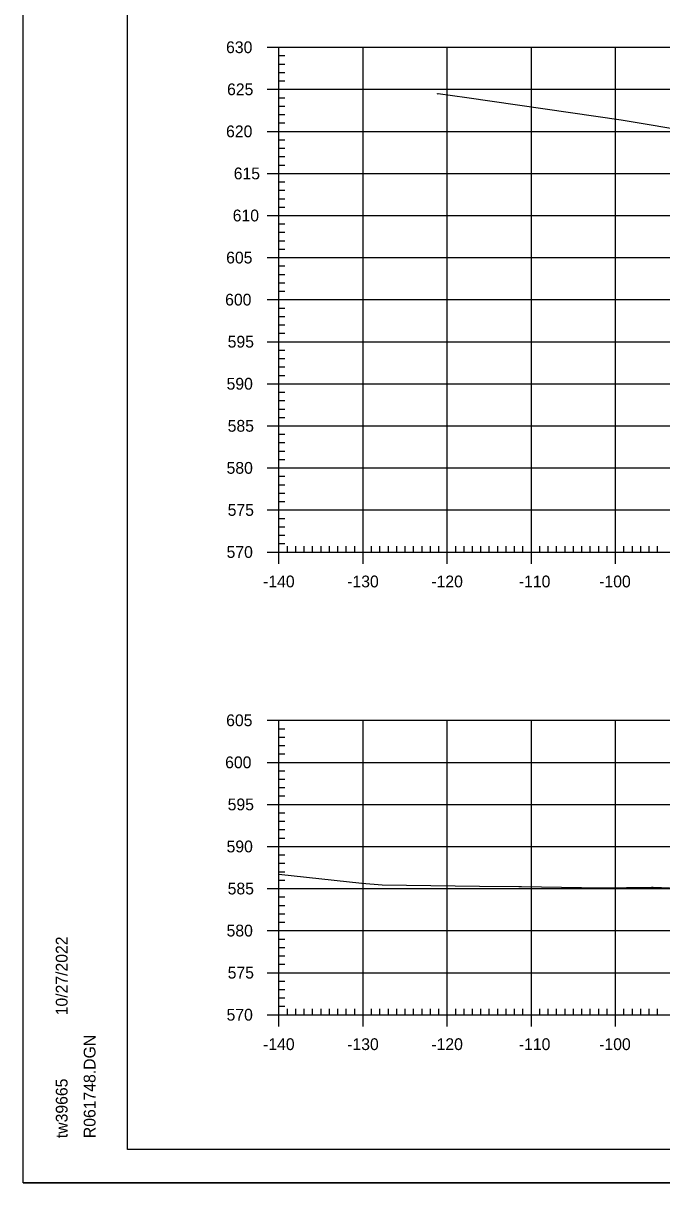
# Model space of a CAD drawing. Extents: x 961436 to 1372525, y 380079 to 2027791.
# Drawn here: x 1370463.4 to 1370539.3, y 380535.8 to 380673.6 of the extents above; entities that cross this region are included whole.
import ezdxf

# ---------------------------------------------------------------- set-up
doc = ezdxf.new("R2010")
doc.units = 0
for name, color, linetype in [('R_Axis', 7, 'Continuous'), ('R_Axis Annot', 7, 'Continuous'), ('R_Exist Surface', 7, 'Continuous'), ('R_Grid', 7, 'Continuous'), ('R_No Plot', 7, 'Continuous')]:
    doc.layers.add(name, color=color, linetype=linetype)

msp = doc.modelspace()

# ---------------------------------------------------------------- linework, layer by layer
at = {"layer": 'R_Axis'}
for p, q in [((1370492.41, 380670.73), (1370495.21, 380670.73)), ((1370493.81, 380610.73), (1370493.81, 380670.73)), ((1370493.81, 380669.73), (1370494.51, 380669.73)), ((1370493.81, 380668.73), (1370494.51, 380668.73)), ((1370493.81, 380667.73), (1370494.51, 380667.73)), ((1370493.81, 380666.73), (1370494.51, 380666.73)), ((1370492.41, 380665.73), (1370495.21, 380665.73)), ((1370493.81, 380664.73), (1370494.51, 380664.73)), ((1370493.81, 380663.73), (1370494.51, 380663.73)), ((1370493.81, 380662.73), (1370494.51, 380662.73)), ((1370493.81, 380661.73), (1370494.51, 380661.73)), ((1370492.41, 380660.73), (1370495.21, 380660.73)), ((1370493.81, 380659.73), (1370494.51, 380659.73)), ((1370493.81, 380658.73), (1370494.51, 380658.73)), ((1370493.81, 380657.73), (1370494.51, 380657.73)), ((1370493.81, 380656.73), (1370494.51, 380656.73)), ((1370492.41, 380655.73), (1370495.21, 380655.73)), ((1370493.81, 380654.73), (1370494.51, 380654.73)), ((1370493.81, 380653.73), (1370494.51, 380653.73)), ((1370493.81, 380652.73), (1370494.51, 380652.73)), ((1370493.81, 380651.73), (1370494.51, 380651.73)), ((1370492.41, 380650.73), (1370495.21, 380650.73)), ((1370493.81, 380649.73), (1370494.51, 380649.73)), ((1370493.81, 380648.73), (1370494.51, 380648.73)), ((1370493.81, 380647.73), (1370494.51, 380647.73)), ((1370492.41, 380645.73), (1370495.21, 380645.73)), ((1370493.81, 380646.73), (1370494.51, 380646.73)), ((1370493.81, 380644.73), (1370494.51, 380644.73)), ((1370493.81, 380643.73), (1370494.51, 380643.73)), ((1370493.81, 380642.73), (1370494.51, 380642.73)), ((1370493.81, 380641.73), (1370494.51, 380641.73)), ((1370492.41, 380640.73), (1370495.21, 380640.73)), ((1370493.81, 380639.73), (1370494.51, 380639.73)), ((1370493.81, 380638.73), (1370494.51, 380638.73)), ((1370493.81, 380637.73), (1370494.51, 380637.73)), ((1370493.81, 380636.73), (1370494.51, 380636.73)), ((1370492.41, 380635.73), (1370495.21, 380635.73)), ((1370493.81, 380634.73), (1370494.51, 380634.73)), ((1370493.81, 380633.73), (1370494.51, 380633.73)), ((1370493.81, 380632.73), (1370494.51, 380632.73)), ((1370492.41, 380630.73), (1370495.21, 380630.73)), ((1370493.81, 380631.73), (1370494.51, 380631.73)), ((1370493.81, 380629.73), (1370494.51, 380629.73)), ((1370493.81, 380628.73), (1370494.51, 380628.73)), ((1370493.81, 380627.73), (1370494.51, 380627.73)), ((1370493.81, 380626.73), (1370494.51, 380626.73)), ((1370492.41, 380625.73), (1370495.21, 380625.73)), ((1370493.81, 380624.73), (1370494.51, 380624.73)), ((1370493.81, 380623.73), (1370494.51, 380623.73)), ((1370493.81, 380622.73), (1370494.51, 380622.73)), ((1370493.81, 380621.73), (1370494.51, 380621.73)), ((1370492.41, 380620.73), (1370495.21, 380620.73)), ((1370493.81, 380619.73), (1370494.51, 380619.73)), ((1370493.81, 380618.73), (1370494.51, 380618.73)), ((1370493.81, 380617.73), (1370494.51, 380617.73)), ((1370493.81, 380616.73), (1370494.51, 380616.73)), ((1370492.41, 380615.73), (1370495.21, 380615.73)), ((1370493.81, 380614.73), (1370494.51, 380614.73)), ((1370493.81, 380613.73), (1370494.51, 380613.73)), ((1370493.81, 380612.73), (1370494.51, 380612.73)), ((1370493.81, 380609.33), (1370493.81, 380612.13)), ((1370493.81, 380611.73), (1370494.51, 380611.73)), ((1370494.81, 380610.73), (1370494.81, 380611.43)), ((1370495.81, 380610.73), (1370495.81, 380611.43)), ((1370496.81, 380610.73), (1370496.81, 380611.43)), ((1370497.81, 380610.73), (1370497.81, 380611.43)), ((1370498.81, 380610.73), (1370498.81, 380611.43)), ((1370499.81, 380610.73), (1370499.81, 380611.43)), ((1370500.81, 380610.73), (1370500.81, 380611.43)), ((1370501.81, 380610.73), (1370501.81, 380611.43)), ((1370502.81, 380610.73), (1370502.81, 380611.43)), ((1370503.81, 380609.33), (1370503.81, 380612.13)), ((1370504.81, 380610.73), (1370504.81, 380611.43)), ((1370505.81, 380610.73), (1370505.81, 380611.43)), ((1370506.81, 380610.73), (1370506.81, 380611.43)), ((1370507.81, 380610.73), (1370507.81, 380611.43)), ((1370508.81, 380610.73), (1370508.81, 380611.43)), ((1370509.81, 380610.73), (1370509.81, 380611.43)), ((1370510.81, 380610.73), (1370510.81, 380611.43)), ((1370511.81, 380610.73), (1370511.81, 380611.43)), ((1370512.81, 380610.73), (1370512.81, 380611.43)), ((1370513.81, 380609.33), (1370513.81, 380612.13)), ((1370514.81, 380610.73), (1370514.81, 380611.43)), ((1370515.81, 380610.73), (1370515.81, 380611.43)), ((1370516.81, 380610.73), (1370516.81, 380611.43)), ((1370517.81, 380610.73), (1370517.81, 380611.43)), ((1370518.81, 380610.73), (1370518.81, 380611.43)), ((1370519.81, 380610.73), (1370519.81, 380611.43)), ((1370520.81, 380610.73), (1370520.81, 380611.43)), ((1370521.81, 380610.73), (1370521.81, 380611.43)), ((1370522.81, 380610.73), (1370522.81, 380611.43)), ((1370523.81, 380609.33), (1370523.81, 380612.13)), ((1370524.81, 380610.73), (1370524.81, 380611.43)), ((1370525.81, 380610.73), (1370525.81, 380611.43)), ((1370526.81, 380610.73), (1370526.81, 380611.43)), ((1370527.81, 380610.73), (1370527.81, 380611.43)), ((1370528.81, 380610.73), (1370528.81, 380611.43)), ((1370529.81, 380610.73), (1370529.81, 380611.43)), ((1370530.81, 380610.73), (1370530.81, 380611.43)), ((1370531.81, 380610.73), (1370531.81, 380611.43)), ((1370532.81, 380610.73), (1370532.81, 380611.43)), ((1370533.81, 380609.33), (1370533.81, 380612.13)), ((1370534.81, 380610.73), (1370534.81, 380611.43)), ((1370535.81, 380610.73), (1370535.81, 380611.43)), ((1370536.81, 380610.73), (1370536.81, 380611.43)), ((1370537.81, 380610.73), (1370537.81, 380611.43)), ((1370538.81, 380610.73), (1370538.81, 380611.43)), ((1370492.41, 380610.73), (1370495.21, 380610.73)), ((1370493.81, 380610.73), (1370773.81, 380610.73)), ((1370492.41, 380590.73), (1370495.21, 380590.73)), ((1370493.81, 380555.73), (1370493.81, 380590.73)), ((1370493.81, 380589.73), (1370494.51, 380589.73)), ((1370493.81, 380588.73), (1370494.51, 380588.73)), ((1370493.81, 380587.73), (1370494.51, 380587.73)), ((1370493.81, 380586.73), (1370494.51, 380586.73)), ((1370492.41, 380585.73), (1370495.21, 380585.73)), ((1370493.81, 380584.73), (1370494.51, 380584.73)), ((1370493.81, 380583.73), (1370494.51, 380583.73)), ((1370493.81, 380582.73), (1370494.51, 380582.73)), ((1370493.81, 380581.73), (1370494.51, 380581.73)), ((1370492.41, 380580.73), (1370495.21, 380580.73)), ((1370493.81, 380579.73), (1370494.51, 380579.73)), ((1370493.81, 380578.73), (1370494.51, 380578.73)), ((1370493.81, 380577.73), (1370494.51, 380577.73)), ((1370493.81, 380576.73), (1370494.51, 380576.73)), ((1370492.41, 380575.73), (1370495.21, 380575.73)), ((1370493.81, 380574.73), (1370494.51, 380574.73)), ((1370493.81, 380573.73), (1370494.51, 380573.73)), ((1370493.81, 380572.73), (1370494.51, 380572.73)), ((1370493.81, 380571.73), (1370494.51, 380571.73)), ((1370492.41, 380570.73), (1370495.21, 380570.73)), ((1370493.81, 380569.73), (1370494.51, 380569.73)), ((1370493.81, 380568.73), (1370494.51, 380568.73)), ((1370493.81, 380567.73), (1370494.51, 380567.73)), ((1370492.41, 380565.73), (1370495.21, 380565.73)), ((1370493.81, 380566.73), (1370494.51, 380566.73)), ((1370493.81, 380564.73), (1370494.51, 380564.73)), ((1370493.81, 380563.73), (1370494.51, 380563.73)), ((1370493.81, 380562.73), (1370494.51, 380562.73)), ((1370493.81, 380561.73), (1370494.51, 380561.73)), ((1370492.41, 380560.73), (1370495.21, 380560.73)), ((1370493.81, 380559.73), (1370494.51, 380559.73)), ((1370493.81, 380558.73), (1370494.51, 380558.73)), ((1370493.81, 380557.73), (1370494.51, 380557.73)), ((1370493.81, 380554.33), (1370493.81, 380557.13)), ((1370493.81, 380556.73), (1370494.51, 380556.73)), ((1370494.81, 380555.73), (1370494.81, 380556.43)), ((1370495.81, 380555.73), (1370495.81, 380556.43)), ((1370496.81, 380555.73), (1370496.81, 380556.43)), ((1370497.81, 380555.73), (1370497.81, 380556.43)), ((1370498.81, 380555.73), (1370498.81, 380556.43)), ((1370499.81, 380555.73), (1370499.81, 380556.43)), ((1370500.81, 380555.73), (1370500.81, 380556.43)), ((1370501.81, 380555.73), (1370501.81, 380556.43)), ((1370502.81, 380555.73), (1370502.81, 380556.43)), ((1370503.81, 380554.33), (1370503.81, 380557.13)), ((1370504.81, 380555.73), (1370504.81, 380556.43)), ((1370505.81, 380555.73), (1370505.81, 380556.43)), ((1370506.81, 380555.73), (1370506.81, 380556.43)), ((1370507.81, 380555.73), (1370507.81, 380556.43)), ((1370508.81, 380555.73), (1370508.81, 380556.43)), ((1370509.81, 380555.73), (1370509.81, 380556.43)), ((1370510.81, 380555.73), (1370510.81, 380556.43)), ((1370511.81, 380555.73), (1370511.81, 380556.43)), ((1370512.81, 380555.73), (1370512.81, 380556.43)), ((1370513.81, 380554.33), (1370513.81, 380557.13)), ((1370514.81, 380555.73), (1370514.81, 380556.43)), ((1370515.81, 380555.73), (1370515.81, 380556.43)), ((1370516.81, 380555.73), (1370516.81, 380556.43)), ((1370517.81, 380555.73), (1370517.81, 380556.43)), ((1370518.81, 380555.73), (1370518.81, 380556.43)), ((1370519.81, 380555.73), (1370519.81, 380556.43)), ((1370520.81, 380555.73), (1370520.81, 380556.43)), ((1370521.81, 380555.73), (1370521.81, 380556.43)), ((1370522.81, 380555.73), (1370522.81, 380556.43)), ((1370523.81, 380554.33), (1370523.81, 380557.13)), ((1370524.81, 380555.73), (1370524.81, 380556.43)), ((1370525.81, 380555.73), (1370525.81, 380556.43)), ((1370526.81, 380555.73), (1370526.81, 380556.43)), ((1370527.81, 380555.73), (1370527.81, 380556.43)), ((1370528.81, 380555.73), (1370528.81, 380556.43)), ((1370529.81, 380555.73), (1370529.81, 380556.43)), ((1370530.81, 380555.73), (1370530.81, 380556.43)), ((1370531.81, 380555.73), (1370531.81, 380556.43)), ((1370532.81, 380555.73), (1370532.81, 380556.43)), ((1370533.81, 380554.33), (1370533.81, 380557.13)), ((1370534.81, 380555.73), (1370534.81, 380556.43)), ((1370535.81, 380555.73), (1370535.81, 380556.43)), ((1370536.81, 380555.73), (1370536.81, 380556.43)), ((1370537.81, 380555.73), (1370537.81, 380556.43)), ((1370538.81, 380555.73), (1370538.81, 380556.43)), ((1370492.41, 380555.73), (1370495.21, 380555.73)), ((1370493.81, 380555.73), (1370773.81, 380555.73))]:
    msp.add_line(p, q, dxfattribs=at)
at = {"layer": 'R_Exist Surface'}
for points in [[(1370512.63, 380665.19), (1370512.72, 380665.22), (1370516.12, 380664.77), (1370534.5, 380662.1), (1370543.25, 380660.62), (1370556.94, 380657.95), (1370557.59, 380657.83), (1370567.58, 380654.59), (1370574.09, 380652.45), (1370576.45, 380651.83), (1370582.07, 380649.88), (1370582.5, 380649.65), (1370582.67, 380649.59), (1370598.06, 380642.65), (1370599.3, 380642.32), (1370600.61, 380641.87), (1370609.53, 380638.55), (1370609.84, 380638.41), (1370613.14, 380636.72), (1370613.88, 380636.59), (1370615.54, 380636.34)], [(1370493.81, 380572.45), (1370503.67, 380571.36), (1370506.06, 380571.17), (1370517.65, 380571.01), (1370522.33, 380570.99), (1370522.63, 380570.98), (1370532.15, 380570.82), (1370538.09, 380570.9), (1370538.28, 380570.88), (1370544.15, 380570.65), (1370550.78, 380570.53), (1370551.02, 380570.54), (1370562.34, 380570.37), (1370563.94, 380570.35), (1370565.73, 380570.21), (1370571.12, 380570.24), (1370578.96, 380570.23), (1370586.9, 380569.19), (1370588.49, 380569.08), (1370589.31, 380569.11), (1370590.68, 380569.57), (1370597.64, 380572.88), (1370613.16, 380581.5), (1370619.52, 380581.98)]]:
    msp.add_lwpolyline(points, dxfattribs=at)
at = {"layer": 'R_Grid'}
for p, q in [((1370493.81, 380670.73), (1370773.81, 380670.73)), ((1370493.81, 380610.73), (1370493.81, 380670.73)), ((1370503.81, 380610.73), (1370503.81, 380670.73)), ((1370513.81, 380610.73), (1370513.81, 380670.73)), ((1370523.81, 380610.73), (1370523.81, 380670.73)), ((1370533.81, 380610.73), (1370533.81, 380670.73)), ((1370493.81, 380665.73), (1370773.81, 380665.73)), ((1370493.81, 380660.73), (1370773.81, 380660.73)), ((1370493.81, 380655.73), (1370773.81, 380655.73)), ((1370493.81, 380650.73), (1370773.81, 380650.73)), ((1370493.81, 380645.73), (1370773.81, 380645.73)), ((1370493.81, 380640.73), (1370773.81, 380640.73)), ((1370493.81, 380635.73), (1370773.81, 380635.73)), ((1370493.81, 380630.73), (1370773.81, 380630.73)), ((1370493.81, 380625.73), (1370773.81, 380625.73)), ((1370493.81, 380620.73), (1370773.81, 380620.73)), ((1370493.81, 380615.73), (1370773.81, 380615.73)), ((1370493.81, 380610.73), (1370773.81, 380610.73)), ((1370493.81, 380590.73), (1370773.81, 380590.73)), ((1370493.81, 380555.73), (1370493.81, 380590.73)), ((1370503.81, 380555.73), (1370503.81, 380590.73)), ((1370513.81, 380555.73), (1370513.81, 380590.73)), ((1370523.81, 380555.73), (1370523.81, 380590.73)), ((1370533.81, 380555.73), (1370533.81, 380590.73)), ((1370493.81, 380585.73), (1370773.81, 380585.73)), ((1370493.81, 380580.73), (1370773.81, 380580.73)), ((1370493.81, 380575.73), (1370773.81, 380575.73)), ((1370493.81, 380570.73), (1370773.81, 380570.73)), ((1370493.81, 380565.73), (1370773.81, 380565.73)), ((1370493.81, 380560.73), (1370773.81, 380560.73)), ((1370493.81, 380555.73), (1370773.81, 380555.73))]:
    msp.add_line(p, q, dxfattribs=at)
at = {"layer": 'R_No Plot'}
for p, q in [((1370475.81, 380539.73), (1370475.81, 380745.19)), ((1370475.81, 380539.73), (1370475.81, 380539.73)), ((1370791.99, 380539.73), (1370475.81, 380539.73)), ((1370463.41, 380535.76), (1370796.74, 380535.76))]:
    msp.add_line(p, q, dxfattribs=at)
for points in [[(1370463.4, 380749.09), (1370796.74, 380749.09), (1370796.74, 380535.75), (1370463.4, 380535.75)], [(1370709.73, 380745.19), (1370729.35, 380745.19), (1370729.35, 380735.31), (1370745.46, 380735.31), (1370768.66, 380735.31), (1370768.78, 380707.16), (1370791.99, 380707.16), (1370791.99, 380539.73), (1370475.81, 380539.73), (1370475.81, 380745.19)]]:
    msp.add_lwpolyline(points, close=True, dxfattribs=at)

# ---------------------------------------------------------------- texts
at = {"layer": 'R_Axis Annot'}
for s, p in [('630', (1370487.52, 380670.03)), ('625', (1370487.64, 380665.03)), ('620', (1370487.52, 380660.03)), ('615', (1370488.43, 380655.03)), ('610', (1370488.31, 380650.03)), ('605', (1370487.53, 380645.03)), ('600', (1370487.41, 380640.03)), ('595', (1370487.71, 380635.03)), ('590', (1370487.58, 380630.03)), ('585', (1370487.71, 380625.03)), ('580', (1370487.58, 380620.03)), ('575', (1370487.71, 380615.03)), ('570', (1370487.58, 380610.03)), ('-140', (1370491.92, 380606.53)), ('-130', (1370501.92, 380606.53)), ('-120', (1370511.92, 380606.53)), ('-110', (1370522.32, 380606.53)), ('-100', (1370531.87, 380606.53)), ('605', (1370487.53, 380590.03)), ('600', (1370487.41, 380585.03)), ('595', (1370487.71, 380580.03)), ('590', (1370487.58, 380575.03)), ('585', (1370487.71, 380570.03)), ('580', (1370487.58, 380565.03)), ('575', (1370487.71, 380560.03)), ('570', (1370487.58, 380555.03)), ('-140', (1370491.92, 380551.53)), ('-130', (1370501.92, 380551.53)), ('-120', (1370511.92, 380551.53)), ('-110', (1370522.32, 380551.53)), ('-100', (1370531.87, 380551.53))]:
    msp.add_text(s, height=1.4, dxfattribs=at).set_placement(p)
at = {"layer": 'R_No Plot'}
for s, p in [('10/27/2022', (1370468.68, 380555.66)), ('R061748.DGN', (1370472, 380541.06)), ('tw39665', (1370468.68, 380541.06))]:
    msp.add_text(s, height=1.4, rotation=90, dxfattribs=at).set_placement(p)

doc.saveas('drawing.dxf')
